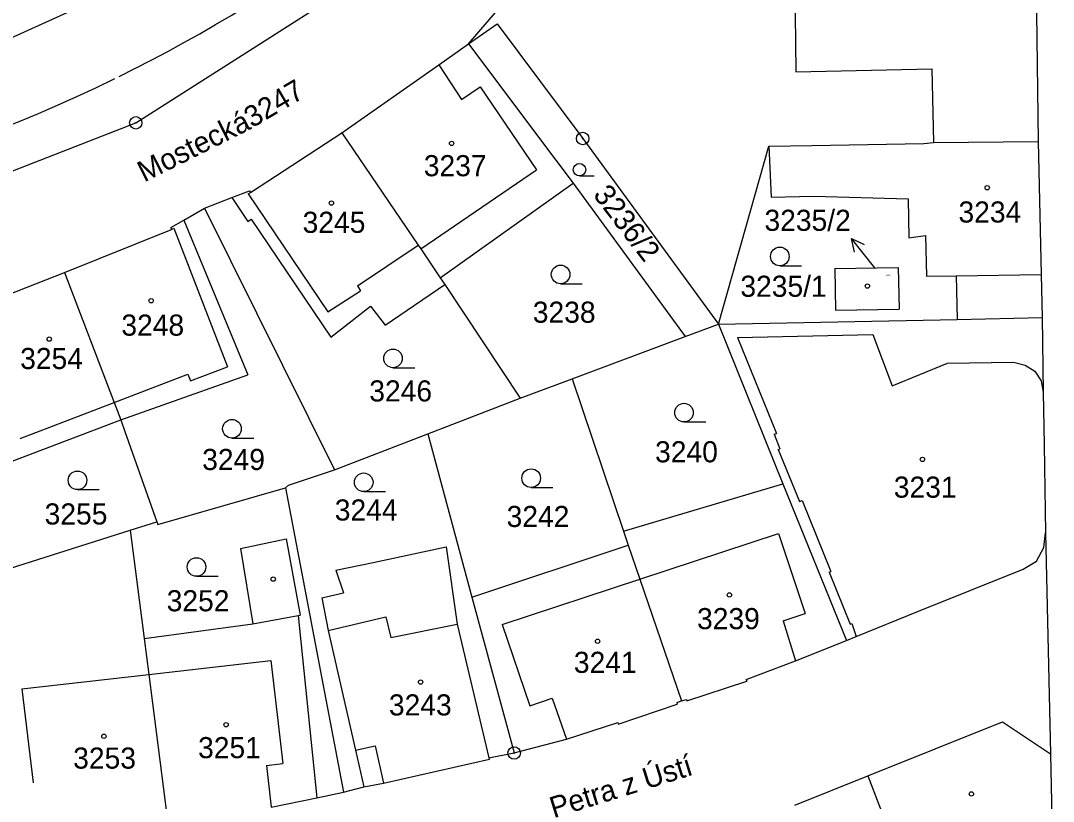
# Model space of a CAD drawing. Extents: x -735092 to -733385, y -1122435 to -1118992.
# Drawn here: x -734532.2 to -734449, y -1120271.1 to -1120208.2 of the extents above; entities that cross this region are included whole.
import ezdxf

# ---------------------------------------------------------------- set-up
doc = ezdxf.new("R2010")
doc.units = 0
for name, color, linetype in [('Vrstva 1', 7, 'Continuous'), ('Vrstva 10', 7, 'Continuous'), ('Vrstva 15', 7, 'Continuous'), ('Vrstva 16', 7, 'Continuous'), ('Vrstva 18', 7, 'Continuous'), ('Vrstva 19', 7, 'Continuous'), ('Vrstva 25', 7, 'Continuous'), ('Vrstva 4', 7, 'Continuous')]:
    doc.layers.add(name, color=color, linetype=linetype)

msp = doc.modelspace()

# ---------------------------------------------------------------- linework, layer by layer
at = {"layer": 'Vrstva 1'}
for points in [[(-734496.12, -1120210.08), (-734486.59, -1120198.98)], [(-734522.92, -1120216.44), (-734500.69, -1120202.26)], [(-734542.11, -1120213.74), (-734525.37, -1120206.12)], [(-734450.37, -1120207.58), (-734450.23, -1120217.95)], [(-734496.12, -1120210.08), (-734493.8, -1120208.46)], [(-734493.8, -1120208.46), (-734486.92, -1120217.7)], [(-734498.52, -1120211.77), (-734496.12, -1120210.08)], [(-734496.12, -1120210.08), (-734489.09, -1120219.44)], [(-734506.33, -1120217.25), (-734498.52, -1120211.77)], [(-734543.71, -1120224.54), (-734522.92, -1120216.44)], [(-734513.68, -1120222.04), (-734506.33, -1120217.25)], [(-734506.33, -1120217.25), (-734500.16, -1120226.29)], [(-734486.92, -1120217.7), (-734475.99, -1120232.66)], [(-734459.44, -1120218.11), (-734458.67, -1120218.03)], [(-734458.67, -1120218.03), (-734450.23, -1120217.95)], [(-734450.23, -1120217.95), (-734449.99, -1120228.65)], [(-734475.99, -1120232.66), (-734471.92, -1120218.33)], [(-734471.92, -1120218.33), (-734468.46, -1120218.27)], [(-734471.92, -1120218.33), (-734471.75, -1120222.42)], [(-734468.46, -1120218.27), (-734459.44, -1120218.11)], [(-734489.09, -1120219.44), (-734487.7, -1120221.3)], [(-734498.39, -1120228.91), (-734487.7, -1120221.3)], [(-734487.7, -1120221.3), (-734478.67, -1120233.66)], [(-734515.18, -1120222.46), (-734513.77, -1120221.91)], [(-734513.77, -1120221.91), (-734513.68, -1120222.04)], [(-734517.37, -1120223.32), (-734515.18, -1120222.46)], [(-734515.18, -1120222.46), (-734513.88, -1120224.38)], [(-734471.75, -1120222.42), (-734468.3, -1120222.35)], [(-734468.3, -1120222.35), (-734460.7, -1120222.55)], [(-734460.7, -1120222.55), (-734460.64, -1120225.71)], [(-734519.05, -1120224.27), (-734517.37, -1120223.32)], [(-734517.37, -1120223.32), (-734506.91, -1120244.39)], [(-734520.09, -1120224.86), (-734519.05, -1120224.27)], [(-734519.05, -1120224.27), (-734513.89, -1120236.74)], [(-734513.88, -1120224.38), (-734513.63, -1120224.21)], [(-734513.63, -1120224.21), (-734507.21, -1120233.7)], [(-734528.66, -1120228.48), (-734520.03, -1120225.02)], [(-734520.09, -1120224.86), (-734520.03, -1120225.02)], [(-734460.64, -1120225.71), (-734459.3, -1120225.51)], [(-734459.3, -1120225.51), (-734459.24, -1120228.79)], [(-734500.16, -1120226.29), (-734499.96, -1120226.59)], [(-734499.96, -1120226.59), (-734498.39, -1120228.91)], [(-734535.59, -1120231.21), (-734528.66, -1120228.48)], [(-734528.66, -1120228.48), (-734524.66, -1120238.96)], [(-734466.61, -1120228.18), (-734461.5, -1120228.09)], [(-734466.61, -1120228.18), (-734466.56, -1120231.54)], [(-734461.5, -1120228.09), (-734461.44, -1120231.44)], [(-734459.24, -1120228.79), (-734456.84, -1120228.75)], [(-734456.84, -1120228.75), (-734456.77, -1120232.27)], [(-734449.99, -1120228.65), (-734449.91, -1120232.13)], [(-734502.82, -1120232.73), (-734498.03, -1120229.45)], [(-734498.39, -1120228.91), (-734498.03, -1120229.45)], [(-734498.03, -1120229.45), (-734491.96, -1120238.61)], [(-734507.21, -1120233.7), (-734504.01, -1120231.2)], [(-734504.01, -1120231.2), (-734502.82, -1120232.73)], [(-734466.56, -1120231.54), (-734461.44, -1120231.44)], [(-734456.77, -1120232.27), (-734449.91, -1120232.13)], [(-734449.91, -1120232.13), (-734449.82, -1120238.13)], [(-734478.67, -1120233.66), (-734475.99, -1120232.66)], [(-734475.99, -1120232.66), (-734456.77, -1120232.27)], [(-734475.99, -1120232.66), (-734470.79, -1120245.51)], [(-734487.77, -1120237.05), (-734478.67, -1120233.66)], [(-734524.13, -1120240.37), (-734513.89, -1120236.74)], [(-734491.96, -1120238.61), (-734487.77, -1120237.05)], [(-734487.77, -1120237.05), (-734483.64, -1120249.33)], [(-734499.39, -1120241.49), (-734491.96, -1120238.61)], [(-734449.82, -1120238.13), (-734449.76, -1120242.38)], [(-734524.66, -1120238.96), (-734524.13, -1120240.37)], [(-734532.88, -1120243.7), (-734524.13, -1120240.37)], [(-734524.13, -1120240.37), (-734523.79, -1120241.29)], [(-734523.79, -1120241.29), (-734521.21, -1120248.57)], [(-734506.91, -1120244.39), (-734499.39, -1120241.49)], [(-734499.39, -1120241.49), (-734495.84, -1120254.63)], [(-734449.76, -1120242.38), (-734449.65, -1120249.47)], [(-734510.61, -1120245.62), (-734506.91, -1120244.39)], [(-734483.64, -1120249.33), (-734470.79, -1120245.51)], [(-734470.79, -1120245.51), (-734465.68, -1120258.12)], [(-734521.13, -1120248.8), (-734510.86, -1120245.84)], [(-734510.86, -1120245.84), (-734510.61, -1120245.62)], [(-734510.86, -1120245.84), (-734506.18, -1120270.34)], [(-734523.37, -1120249.25), (-734521.21, -1120248.57)], [(-734521.21, -1120248.57), (-734521.13, -1120248.8)], [(-734534.81, -1120252.87), (-734523.37, -1120249.25)], [(-734523.37, -1120249.25), (-734522.24, -1120257.98)], [(-734483.64, -1120249.33), (-734483.26, -1120250.45)], [(-734449.78, -1120250.64), (-734449.65, -1120249.47)], [(-734449.65, -1120249.47), (-734449.23, -1120267.25)], [(-734514.49, -1120250.72), (-734510.8, -1120249.95)], [(-734510.8, -1120249.95), (-734509.67, -1120256.08)], [(-734495.84, -1120254.63), (-734483.26, -1120250.45)], [(-734483.26, -1120250.45), (-734482.33, -1120253.19)], [(-734514.49, -1120250.72), (-734513.48, -1120256.78)], [(-734503.79, -1120251.84), (-734497.93, -1120250.59)], [(-734497.93, -1120250.59), (-734497.02, -1120256.81)], [(-734450.36, -1120251.73), (-734449.78, -1120250.64)], [(-734506.81, -1120252.46), (-734503.79, -1120251.84)], [(-734451.43, -1120252.38), (-734450.36, -1120251.73)], [(-734506.81, -1120252.46), (-734506.2, -1120254.29)], [(-734459.87, -1120255.78), (-734451.43, -1120252.38)], [(-734482.33, -1120253.19), (-734478.95, -1120263)], [(-734507.93, -1120254.69), (-734506.2, -1120254.29)], [(-734495.84, -1120254.63), (-734492.44, -1120267.19)], [(-734507.93, -1120254.69), (-734507.43, -1120257.32)], [(-734509.85, -1120256.11), (-734509.67, -1120256.08)], [(-734509.85, -1120256.11), (-734508.33, -1120270.79)], [(-734464.88, -1120257.8), (-734459.87, -1120255.78)], [(-734522.24, -1120257.98), (-734513.48, -1120256.78)], [(-734497.02, -1120256.81), (-734494.47, -1120267.58)], [(-734522.24, -1120257.98), (-734521.87, -1120260.86)], [(-734507.43, -1120257.32), (-734505.22, -1120266.97)], [(-734465.68, -1120258.12), (-734464.88, -1120257.8)], [(-734469.78, -1120259.77), (-734465.68, -1120258.12)], [(-734473.75, -1120261.27), (-734469.78, -1120259.77)], [(-734521.87, -1120260.86), (-734520.4, -1120272.42)], [(-734473.75, -1120261.27), (-734473.7, -1120261.4)], [(-734478.52, -1120263), (-734473.7, -1120261.4)], [(-734478.95, -1120263), (-734478.56, -1120262.88)], [(-734478.56, -1120262.88), (-734478.52, -1120263)], [(-734484.05, -1120264.86), (-734479.3, -1120263.26)], [(-734479.34, -1120263.13), (-734478.95, -1120263)], [(-734479.34, -1120263.13), (-734479.3, -1120263.26)], [(-734488.23, -1120266.07), (-734484.09, -1120264.74)], [(-734484.09, -1120264.74), (-734484.05, -1120264.86)], [(-734463.95, -1120269.02), (-734453.1, -1120264.68)], [(-734453.1, -1120264.68), (-734449.23, -1120267.25)], [(-734492.44, -1120267.19), (-734488.23, -1120266.07)], [(-734505.22, -1120266.97), (-734504.55, -1120269.91)], [(-734502.96, -1120269.61), (-734494.44, -1120267.69)], [(-734494.47, -1120267.58), (-734492.44, -1120267.19)], [(-734494.47, -1120267.58), (-734494.44, -1120267.69)], [(-734449.23, -1120267.25), (-734449.01, -1120278.95)], [(-734504.55, -1120269.91), (-734502.96, -1120269.61)], [(-734469.82, -1120271.38), (-734463.95, -1120269.02)], [(-734463.95, -1120269.02), (-734461.29, -1120275.96)], [(-734508.33, -1120270.79), (-734506.18, -1120270.34)], [(-734506.18, -1120270.34), (-734504.55, -1120269.91)], [(-734512, -1120271.55), (-734508.33, -1120270.79)]]:
    msp.add_lwpolyline(points, dxfattribs=at)
at = {"layer": 'Vrstva 10'}
for centre, radius, start, end in [((-734582.246, -1120095.461), 130.798, 296.31569, 316.89139), ((-734577.688, -1120104.718), 120.479, 270.49893, 296.13651)]:
    msp.add_arc(centre, radius, start, end, dxfattribs=at)
at = {"layer": 'Vrstva 25'}
for points in [[(-734487.18, -1120220.72), (-734486.007, -1120220.72)], [(-734463.4, -1120228.11), (-734465.255, -1120225.753)], [(-734465.029, -1120226.848), (-734465.255, -1120225.753), (-734464.243, -1120226.23)], [(-734471.04, -1120227.95), (-734469.29, -1120227.95)], [(-734488.7, -1120229.4), (-734486.95, -1120229.4)], [(-734502.2, -1120236.16), (-734500.45, -1120236.16)], [(-734478.76, -1120240.53), (-734477.01, -1120240.53)], [(-734515.17, -1120241.83), (-734513.42, -1120241.83)], [(-734527.61, -1120245.98), (-734525.86, -1120245.98)], [(-734504.56, -1120246.14), (-734502.81, -1120246.14)], [(-734491.07, -1120245.81), (-734489.32, -1120245.81)], [(-734518.03, -1120252.96), (-734516.28, -1120252.96)]]:
    msp.add_lwpolyline(points, dxfattribs=at)
for centre, radius in [((-734522.92, -1120216.44), 0.5), ((-734522.92, -1120216.44), 0.032), ((-734486.92, -1120217.7), 0.5), ((-734497.48, -1120218.1), 0.175), ((-734486.92, -1120217.7), 0.032), ((-734487.179, -1120220.218), 0.503), ((-734454.34, -1120221.67), 0.175), ((-734507.16, -1120222.9), 0.175), ((-734471.04, -1120227.2), 0.75), ((-734488.7, -1120228.65), 0.75), ((-734463.99, -1120229.59), 0.175), ((-734521.68, -1120230.77), 0.175), ((-734529.89, -1120233.86), 0.175), ((-734502.2, -1120235.41), 0.75), ((-734478.76, -1120239.78), 0.75), ((-734515.17, -1120241.08), 0.75), ((-734459.55, -1120243.55), 0.175), ((-734527.61, -1120245.23), 0.75), ((-734504.56, -1120245.39), 0.75), ((-734491.07, -1120245.06), 0.75), ((-734518.03, -1120252.21), 0.75), ((-734511.85, -1120253.19), 0.174), ((-734475.1, -1120254.46), 0.175), ((-734485.72, -1120258.19), 0.175), ((-734499.98, -1120261.48), 0.175), ((-734515.64, -1120264.92), 0.175), ((-734525.49, -1120265.84), 0.175), ((-734492.44, -1120267.19), 0.5), ((-734492.44, -1120267.19), 0.032), ((-734455.61, -1120270.49), 0.175)]:
    msp.add_circle(centre, radius, dxfattribs=at)
at = {"layer": 'Vrstva 4'}
for points in [[(-734469.91, -1120198.38), (-734469.76, -1120212.33)], [(-734498.52, -1120211.77), (-734496.68, -1120214.56)], [(-734469.76, -1120212.33), (-734458.79, -1120212.1)], [(-734458.79, -1120212.1), (-734458.67, -1120218.03)], [(-734496.68, -1120214.56), (-734495.19, -1120213.54)], [(-734495.19, -1120213.54), (-734490.63, -1120220.23)], [(-734499.96, -1120226.59), (-734490.63, -1120220.23)], [(-734513.86, -1120222.16), (-734513.68, -1120222.04)], [(-734513.86, -1120222.16), (-734507.46, -1120231.66)], [(-734520.03, -1120225.02), (-734519.86, -1120224.93)], [(-734519.86, -1120224.93), (-734515.52, -1120236.1)], [(-734505.06, -1120229.57), (-734500.16, -1120226.29)], [(-734456.84, -1120228.75), (-734449.99, -1120228.65)], [(-734505.06, -1120229.57), (-734504.81, -1120229.96)], [(-734507.46, -1120231.66), (-734504.81, -1120229.96)], [(-734474.45, -1120233.72), (-734463.55, -1120233.49)], [(-734474.45, -1120233.72), (-734471.31, -1120241.45)], [(-734463.55, -1120233.49), (-734462, -1120237.61)], [(-734518.51, -1120237.23), (-734515.52, -1120236.1)], [(-734462, -1120237.61), (-734457.54, -1120235.79)], [(-734457.54, -1120235.79), (-734452.23, -1120235.71)], [(-734452.23, -1120235.71), (-734451.29, -1120235.95)], [(-734451.29, -1120235.95), (-734450.49, -1120236.44)], [(-734524.66, -1120238.96), (-734518.72, -1120236.68)], [(-734518.72, -1120236.68), (-734518.51, -1120237.23)], [(-734450.49, -1120236.44), (-734449.98, -1120237.23)], [(-734449.98, -1120237.23), (-734449.82, -1120238.13)], [(-734532.24, -1120241.86), (-734524.66, -1120238.96)], [(-734471.5, -1120241.52), (-734471.31, -1120241.45)], [(-734471.5, -1120241.52), (-734471.04, -1120242.69)], [(-734471.17, -1120242.75), (-734471.04, -1120242.69)], [(-734471.17, -1120242.75), (-734469.45, -1120246.94)], [(-734469.45, -1120246.94), (-734469.23, -1120246.85)], [(-734469.23, -1120246.85), (-734466.92, -1120252.57)], [(-734482.33, -1120253.19), (-734471.14, -1120249.51)], [(-734471.14, -1120249.51), (-734468.99, -1120255.96)], [(-734467.08, -1120252.64), (-734466.92, -1120252.57)], [(-734467.08, -1120252.64), (-734465.38, -1120256.82)], [(-734493.4, -1120256.84), (-734482.33, -1120253.19)], [(-734513.48, -1120256.78), (-734509.85, -1120256.11)], [(-734507.43, -1120257.32), (-734502.77, -1120256.22)], [(-734502.77, -1120256.22), (-734502.37, -1120257.9)], [(-734470.77, -1120256.55), (-734468.99, -1120255.96)], [(-734502.37, -1120257.9), (-734497.02, -1120256.81)], [(-734493.4, -1120256.84), (-734491.18, -1120263.38)], [(-734470.77, -1120256.55), (-734469.78, -1120259.77)], [(-734465.38, -1120256.82), (-734465.23, -1120256.76)], [(-734465.23, -1120256.76), (-734464.88, -1120257.8)], [(-734521.87, -1120260.86), (-734512.04, -1120259.74)], [(-734512.04, -1120259.74), (-734511.08, -1120268.05)], [(-734532.1, -1120262.02), (-734521.87, -1120260.86)], [(-734532.1, -1120262.02), (-734531.18, -1120269.59)], [(-734491.18, -1120263.38), (-734489.37, -1120262.77)], [(-734489.37, -1120262.77), (-734488.23, -1120266.07)], [(-734505.22, -1120266.97), (-734503.64, -1120266.61)], [(-734503.64, -1120266.61), (-734502.96, -1120269.61)], [(-734512.4, -1120268.2), (-734511.08, -1120268.05)], [(-734512.4, -1120268.2), (-734512, -1120271.55)]]:
    msp.add_lwpolyline(points, dxfattribs=at)

# ---------------------------------------------------------------- texts
at = {"layer": 'Vrstva 15'}
for s, height, rotation, p in [('Mostecká', 1.7, 26.60021, (-734522.241, -1120221.252)), ('Petra z Ústí', 1.69999, 17.30014, (-734489.259, -1120272.45))]:
    msp.add_text(s, height=height, rotation=rotation, dxfattribs=at).set_placement(p)
at = {"layer": 'Vrstva 16'}
msp.add_text('3235/2', height=1.7, dxfattribs=at).set_placement((-734472.277, -1120225.14))
at = {"layer": 'Vrstva 18'}
for s, rotation, p in [('3247', 30.50024, (-734513.55, -1120216.887)), ('3236/2', 307.40244, (-734486.14, -1120222.247))]:
    msp.add_text(s, height=1.7, rotation=rotation, dxfattribs=at).set_placement(p)
for s, p in [('3235/1', (-734474.22, -1120230.45)), ('3238', (-734490.94, -1120232.54)), ('3246', (-734504.11, -1120238.88)), ('3240', (-734481.09, -1120243.78)), ('3249', (-734517.57, -1120244.4)), ('3255', (-734530.26, -1120248.79)), ('3244', (-734506.89, -1120248.47)), ('3242', (-734493.05, -1120248.99)), ('3252', (-734520.43, -1120255.78))]:
    msp.add_text(s, height=1.7, dxfattribs=at).set_placement(p)
at = {"layer": 'Vrstva 19'}
for s, height, p in [('3237', 1.7, (-734499.72, -1120220.74)), ('3234', 1.7, (-734456.65, -1120224.47)), ('3245', 1.7, (-734509.48, -1120225.3)), ('3235/2', 0.1, (-734462.51, -1120228.78)), ('3248', 1.7, (-734524.08, -1120233.58)), ('3254', 1.7, (-734532.23, -1120236.27)), ('3231', 1.7, (-734461.86, -1120246.63)), ('3239', 1.7, (-734477.71, -1120257.22)), ('3241', 1.7, (-734487.63, -1120260.74)), ('3243', 1.7, (-734502.53, -1120264.17)), ('3251', 1.7, (-734517.9, -1120267.61)), ('3253', 1.7, (-734527.96, -1120268.45))]:
    msp.add_text(s, height=height, dxfattribs=at).set_placement(p)

doc.saveas('drawing.dxf')
